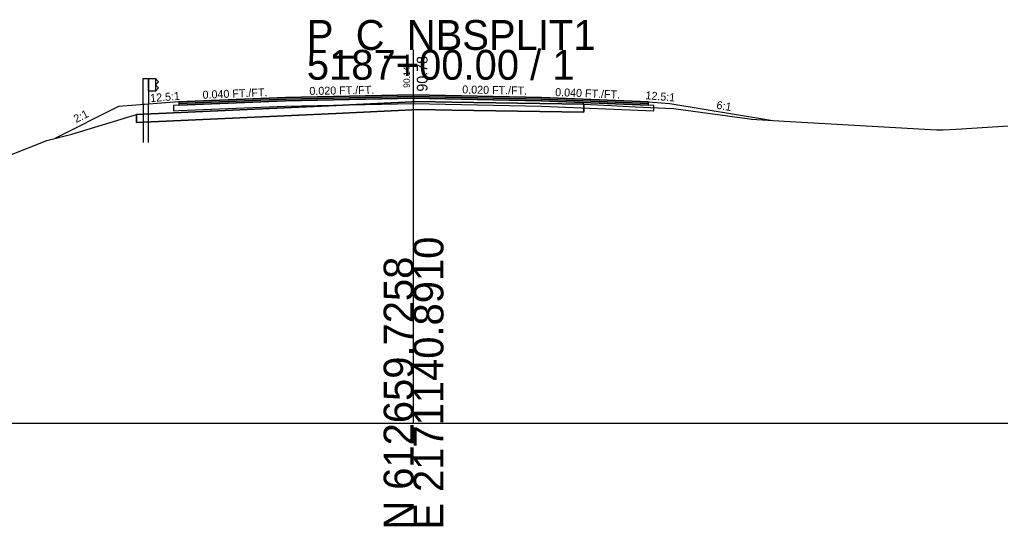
# Model space of a CAD drawing. Extents: x -26 to 1303, y -3010 to 12038.
# Drawn here: x 113.1 to 205, y 6990.3 to 7037.8 of the extents above; entities that cross this region are included whole.
import ezdxf

# ---------------------------------------------------------------- set-up
doc = ezdxf.new("R2010")
doc.units = 0
for name, color, linetype in [('RD_GPK_XS_Cell', 7, 'Continuous'), ('RD_PD_Final_TrvlWay', 7, 'Continuous'), ('RD_XS_Base', 7, 'Continuous'), ('RD_XS_ExGround', 7, 'Continuous'), ('RD_XS_ExPaveRet', 7, 'Continuous'), ('RD_XS_GR', 7, 'Continuous'), ('RD_XS_Greenside', 7, 'Continuous'), ('RD_XS_Pave', 7, 'Continuous'), ('RD_XS_PaveOvlay_CP', 7, 'Continuous'), ('RD_XS_TieSlope', 7, 'Continuous'), ('RD_XS_TX_Elev_EX', 7, 'Continuous'), ('RD_XS_TX_Elev_PR', 7, 'Continuous'), ('RD_XS_TX_ShdSlope', 7, 'Continuous'), ('RD_XS_TX_Slope', 7, 'Continuous')]:
    doc.layers.add(name, color=color, linetype=linetype)

msp = doc.modelspace()

# ---------------------------------------------------------------- linework, layer by layer
at = {"layer": 'RD_GPK_XS_Cell'}
for p, q in [((150, 7000), (150, 7035)), ((0, 7000), (150, 7000)), ((150, 7000), (300, 7000))]:
    msp.add_line(p, q, dxfattribs=at)
at = {"layer": 'RD_PD_Final_TrvlWay'}
for p, q in [((125.167, 7029.911), (124.667, 7029.871)), ((124.667, 7029.871), (124.667, 7026.306)), ((125.167, 7026.306), (125.167, 7029.911))]:
    msp.add_line(p, q, dxfattribs=at)
at = {"layer": 'RD_XS_Base'}
for p, q in [((150, 7030.459), (138, 7030.219)), ((150, 7030.459), (150, 7030.618)), ((150, 7030.618), (150, 7030.618)), ((150, 7030.618), (150, 7030.618)), ((150, 7030.618), (150, 7029.959)), ((150, 7029.959), (150, 7030.459)), ((150, 7030.459), (150, 7030.459)), ((150, 7030.459), (150, 7030.459)), ((150, 7030.459), (150, 7030.459)), ((162, 7030.219), (150, 7030.459)), ((128, 7029.819), (127.5, 7029.799)), ((127.5, 7029.799), (127.5, 7029.799)), ((127.5, 7029.799), (127.5, 7029.299)), ((138, 7030.219), (128, 7029.819)), ((128, 7029.819), (128, 7029.819)), ((128, 7029.319), (138, 7029.719)), ((138, 7030.219), (138, 7030.219)), ((138, 7029.719), (150, 7029.959)), ((138, 7029.719), (138, 7029.719)), ((150, 7029.959), (150, 7029.959)), ((150, 7029.959), (150, 7029.959)), ((150, 7029.959), (162, 7029.719)), ((172, 7029.819), (162, 7030.219)), ((162, 7029.719), (172.5, 7029.299)), ((164, 7030.139), (164, 7030.139)), ((164, 7029.639), (164, 7029.639)), ((172.5, 7029.799), (172, 7029.819)), ((172, 7029.819), (172, 7029.819)), ((172.5, 7029.299), (172.5, 7029.799)), ((172.5, 7029.799), (172.5, 7029.799)), ((127.5, 7029.299), (128, 7029.319)), ((128, 7029.319), (128, 7029.319))]:
    msp.add_line(p, q, dxfattribs=at)
at = {"layer": 'RD_XS_ExGround'}
msp.add_lwpolyline([(112.175, 7025.115), (115.626, 7026.507), (117.966, 7027.097), (124.047, 7028.932), (142.714, 7029.795), (150.494, 7030.158), (153.592, 7030.108), (165.961, 7029.899), (168.522, 7029.787), (170.76, 7029.66), (174.373, 7029.5), (181.254, 7028.555), (181.677, 7028.501), (184.741, 7028.327), (198.99, 7027.503), (199.636, 7027.492), (200.851, 7027.559), (206.207, 7027.905)], dxfattribs=at)
at = {"layer": 'RD_XS_ExPaveRet'}
for p, q in [((150.494, 7030.158), (142.714, 7029.795)), ((165.962, 7029.899), (165.961, 7029.899))]:
    msp.add_line(p, q, dxfattribs=at)
for points in [[(165.962, 7029.899), (165.962, 7029.149), (165.962, 7029.149), (165.961, 7029.149), (153.592, 7029.358), (153.592, 7029.358), (150.494, 7029.408), (150.494, 7029.408), (150.494, 7029.408), (142.714, 7029.045), (142.714, 7029.045), (124.047, 7028.182), (124.047, 7028.932), (124.047, 7028.932), (142.714, 7029.795), (142.714, 7029.795), (150.494, 7030.158), (150.494, 7030.158), (150.494, 7030.158), (153.592, 7030.108), (153.592, 7030.108), (165.961, 7029.899), (165.962, 7029.899)], [(142.714, 7029.795), (124.047, 7028.932), (124.047, 7028.182), (142.714, 7029.045), (150.494, 7029.408), (153.592, 7029.358), (165.961, 7029.149), (165.962, 7029.149), (165.962, 7029.899)], [(165.961, 7029.899), (153.592, 7030.108), (150.494, 7030.158)]]:
    msp.add_lwpolyline(points, dxfattribs=at)
at = {"layer": 'RD_XS_GR'}
for points in [[(125.167, 7032.306), (125.167, 7029.911), (124.667, 7029.871), (124.667, 7032.306), (124.917, 7032.306), (125.167, 7032.306)], [(125.834, 7032.306), (125.834, 7031.139), (125.167, 7031.139), (125.167, 7032.306), (125.834, 7032.306)], [(125.834, 7032.306), (125.834, 7032.306), (125.834, 7032.306), (125.834, 7031.139), (126.105, 7031.431), (126.105, 7031.431), (125.834, 7031.723), (125.834, 7031.723), (126.105, 7032.014), (126.105, 7032.014), (125.834, 7032.306)]]:
    msp.add_lwpolyline(points, dxfattribs=at)
at = {"layer": 'RD_XS_Greenside'}
for p, q in [((122.355, 7029.686), (116.373, 7026.695)), ((174, 7029.977), (183.468, 7028.399))]:
    msp.add_line(p, q, dxfattribs=at)
at = {"layer": 'RD_XS_Pave'}
for p, q in [((138, 7030.537), (128, 7030.137)), ((138, 7030.378), (128, 7029.978)), ((128, 7029.978), (138, 7030.378)), ((150, 7030.777), (138, 7030.537)), ((150, 7030.618), (138, 7030.378)), ((138, 7030.378), (150, 7030.618)), ((138, 7030.537), (138, 7030.537)), ((138, 7030.219), (150, 7030.459)), ((138, 7030.378), (138, 7030.378)), ((138, 7030.378), (138, 7030.378)), ((162, 7030.537), (150, 7030.777)), ((150, 7030.777), (150, 7030.777)), ((150, 7030.777), (150, 7030.777)), ((150, 7030.459), (150, 7030.618)), ((150, 7030.618), (150, 7030.618)), ((150, 7030.618), (150, 7030.618)), ((150, 7030.618), (150, 7030.618)), ((150, 7030.618), (150, 7030.618)), ((150, 7030.618), (162, 7030.378)), ((162, 7030.378), (150, 7030.618)), ((150, 7030.618), (150, 7030.618)), ((150, 7030.618), (150, 7030.618)), ((150, 7030.618), (150, 7030.459)), ((150, 7030.459), (150, 7030.459)), ((150, 7030.459), (150, 7030.459)), ((150, 7030.459), (162, 7030.219)), ((172, 7030.137), (162, 7030.537)), ((162, 7030.378), (172, 7029.978)), ((172, 7029.978), (162, 7030.378)), ((164, 7030.457), (164, 7030.457)), ((164, 7030.298), (164, 7030.298)), ((164, 7030.298), (164, 7030.298)), ((128, 7029.819), (138, 7030.219)), ((128, 7030.137), (128, 7030.137)), ((128, 7030.137), (128, 7029.978)), ((128, 7029.978), (128, 7029.978)), ((128, 7029.978), (128, 7029.819)), ((138, 7030.219), (138, 7030.219)), ((162, 7030.219), (172, 7029.819)), ((164, 7030.139), (164, 7030.139)), ((172, 7029.978), (172, 7030.137)), ((172, 7030.137), (172, 7030.137)), ((172, 7029.819), (172, 7029.978)), ((172, 7029.978), (172, 7029.978))]:
    msp.add_line(p, q, dxfattribs=at)
at = {"layer": 'RD_XS_PaveOvlay_CP'}
for p, q in [((128, 7030.137), (138, 7030.537)), ((138, 7030.537), (150, 7030.777)), ((150, 7030.777), (162, 7030.537)), ((162, 7030.537), (172, 7030.137))]:
    msp.add_line(p, q, dxfattribs=at)
at = {"layer": 'RD_XS_TieSlope'}
for p, q in [((128, 7030.137), (122.355, 7029.686)), ((172, 7030.137), (174, 7029.977))]:
    msp.add_line(p, q, dxfattribs=at)

# ---------------------------------------------------------------- texts
at = {"layer": 'RD_GPK_XS_Cell'}
for s, p in [('P_C_NBSPLIT1', (140, 7035)), ('5187+00.00 / 1', (140, 7032.2))]:
    msp.add_text(s, height=2.8, dxfattribs=at).set_placement(p)
for s, p in [('E 2171140.8910', (152.8, 6990)), ('N 612659.7258', (150, 6990))]:
    msp.add_text(s, height=2.8, rotation=90, dxfattribs=at).set_placement(p)
at = {"layer": 'RD_XS_TX_Elev_EX'}
msp.add_text('90.14', height=0.6, rotation=90, dxfattribs=at).set_placement((149.656, 7031.436))
at = {"layer": 'RD_XS_TX_Elev_PR'}
msp.add_text('90.78', height=1, rotation=90, dxfattribs=at).set_placement((151.307, 7031.083))
at = {"layer": 'RD_XS_TX_ShdSlope'}
for rotation, p in [(4.57392, (125.35, 7030.099)), (355.42608, (171.711, 7030.378))]:
    msp.add_text('12.5:1', height=0.75, rotation=rotation, dxfattribs=at).set_placement(p)
at = {"layer": 'RD_XS_TX_Slope'}
for s, rotation, p in [('0.040 FT./FT.', 2.29061, (130.247, 7030.413)), ('0.020 FT./FT.', 1.14576, (140.248, 7030.768)), ('0.020 FT./FT.', 358.85424, (154.561, 7030.921)), ('0.040 FT./FT.', 357.70939, (163.262, 7030.672)), ('6:1', 350.53768, (178.344, 7029.486)), ('2:1', 26.56505, (118.38, 7028.133))]:
    msp.add_text(s, height=0.75, rotation=rotation, dxfattribs=at).set_placement(p)

doc.saveas('drawing.dxf')
